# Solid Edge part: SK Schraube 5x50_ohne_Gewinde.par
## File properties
Author: fknapp
Template: Normal.par
Last saved by: fknapp
Revision: 18
Application: Solid Edge
Dichte: 0,0000078 kg/mm^3
Genauigkeit: 0,01
Username: fknapp
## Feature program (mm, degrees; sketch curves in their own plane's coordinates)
sketch for "unnamed RevolvedProtrusion 1" plane through (0, 0, 0) normal (0, 0, 1) x-axis (1, 0, 0)
  line (0, 50) -> (4.75, 50)
  line (4.75, 50) -> (4.75, 49)
  line (4.75, 49) -> (2.5, 46.75)
  line (2.5, 46.75) -> (2.5, 6)
  line (2.5, 6) -> (0.2, 0)
  line (0.2, 0) -> (0, 0)
  line (0, 50) -> (0, 0)
revolve "unnamed RevolvedProtrusion 1" add full turn 360 deg
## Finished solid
Body 1: solid body, 6 faces, 5 edges, 0 vertices.
  Faces by surface: cone 2, cylinder 2, plane 2
  Edges by curve: circle 5
Bounding box of the edges (mm): 9.500 x 50.000 x 9.500, from (-4.75, 0, -4.75) to (4.75, 50, 4.75).
Cylindrical faces by radius (mm): R2.5 x1, R4.75 x1
Conical faces (half-angle, radius in mm at the cone's reference point): 20.9735 deg R2.5 x1, 45 deg R4.75 x1
Planar faces by outward normal: +y 1, -y 1
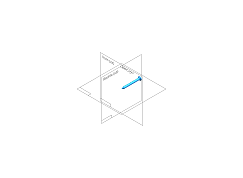
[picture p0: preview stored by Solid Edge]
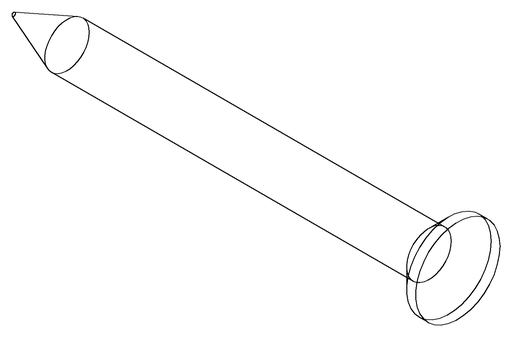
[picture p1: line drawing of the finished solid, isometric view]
